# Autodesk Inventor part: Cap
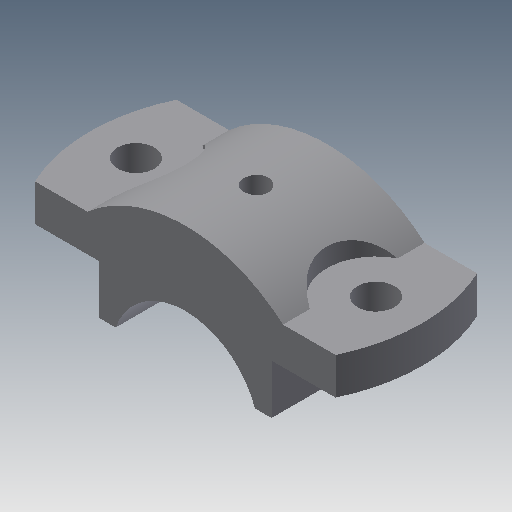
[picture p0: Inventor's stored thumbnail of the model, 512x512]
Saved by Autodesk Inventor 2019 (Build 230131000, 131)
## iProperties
Created: 2009-04
Part Number: Cap
Document SubType Name: Modeling
Designer: Sham
Density: 1 g/cm^3
Material: Generic
Appearance: Default
Mass: 94.0132 g
Surface Area: 184.419 cm^2
Volume: 94.0132 cm^3
Author: Sham
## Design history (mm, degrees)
sketch "Sketch1"
  geometry: L1 (-48.857, 23)-(48.857, 23); L2 (48.857, -23)-(-48.857, -23); A1 r 54 centre (0, 0) between (-48.857, 23) and (-48.857, -23); A2 r 54 centre (0, 0) between (48.857, -23) and (48.857, 23); 1 further point
  constraints: 4 end point, 4 point on circle, 2 centre point, 2 coincident, 1 horizontal, 1 parallel, 1 other
  dimensions: "d3" = 54 radius of A1; "d4" = 54 radius of A2; "d5" = 46 distance between parallel lines of L2 L1; "d6" = 23 distance from line of point (0, 0) L1
extrude "Extrusion1" new body sketch "Sketch1" distance "d7" = 12; taper "d8" = 0 deg
sketch "Sketch3"
  geometry: L1 (20.906, 0)-(20.906, -16); L2 (76.906, -0.137)-(76.906, -16.137); L3 (20.906, -16)-(26.23, -16); L4 (71.532, -16.137)-(76.906, -16.137); L5 (76.906, -0.137)-(76.857, 12); L6 (97.714, 0)-(0, 0) reference; L7 (76.857, 12)-(80.606, 12); L8 (17.108, 12)-(20.906, 12); L9 (20.906, 12)-(20.906, 0); L10 (0, 12)-(97.714, 12) reference; A1 r 24 centre (48.857, -24) between (71.532, -16.137) and (26.23, -16); A2 r 48 centre (48.857, -24) between (80.606, 12) and (17.108, 12); 3 further points
  constraints: 16 end point, 4 point on circle, 3 parallel, 3 perpendicular, 2 centre point, 2 coincident, 2 vertical alignment, 1 collinear, 1 midpoint, 1 vertical, 2 other
  dimensions: "d17" = 48 diameter of A1; "d18" = 16 distance of L1.start L1.end; "d19" = 56 distance between parallel lines of L2 L1; "d21" = 8 vertical distance of A1.centre L1.end; "d22" = 48 radius of A2; "d23" = 0 distance from line of L6 L1.start; "d38" = 31.74902 distance of L7.end point (48.857, 12); "d39" = 28 distance from line of point (48.857, 12) L5
extrude "Extrusion2" join sketch "Sketch3" stored distance "d24" = 12; taper "d25" = 0 deg
sketch "Sketch4"
  geometry: 2 further points
  dimensions: "d26" = 78 distance of point (39, 0) point (-39, 0)
hole "Hole1" sketch "Sketch4" at (-39, 0), (39, 0) diameter "d28" = 12; stored, may be unused: countersink angle "d32" = 90 deg, drill point angle "d34" = 118 deg; dims "d29" = 6, "d30" = 4, "d31" = 2, "d33" = 8
sketch "Sketch5"
  geometry: L1 (-31.749, -23)-(-31.749, 23) reference; L2 (-31.749, 14.263)-(-31.749, -14.263); C1 r 6 at (-39, 0) reference; A1 r 16 centre (-39, 0) between (-31.749, -14.263) and (-31.749, 14.263)
  constraints: 2 end point, 2 point on circle, 1 centre point, 1 coincident, 1 collinear, 1 point on line
  dimensions: "d35" = 16 radius of A1
extrude "Extrusion3" cut sketch "Sketch5" distance "d36" = 12; taper "d37" = 0 deg
mirror "Mirror2"
workplane "Work Plane4"
sketch "Sketch6"
  geometry: L1 (-31.749, 0)-(31.749, 0) reference; 1 further point
  dimensions: "d40" = 23 distance from line of L1 point (0, 23)
hole "Hole2" sketch "Sketch6" at (0, 23) diameter "d41" = 6; stored, may be unused: countersink angle "d45" = 90 deg, drill point angle "d47" = 118 deg; dims "d42" = 6, "d43" = 8, "d44" = 16, "d46" = 8
body "Solid1"
